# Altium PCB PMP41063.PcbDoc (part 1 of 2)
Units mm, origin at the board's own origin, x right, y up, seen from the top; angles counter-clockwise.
Board outline 173.28 x 60.81 mm, 2 copper layers (Top Layer, Bottom Layer), stack 1.575 mm thick; 103 components, 53 nets, 215 pads, 774 vias.
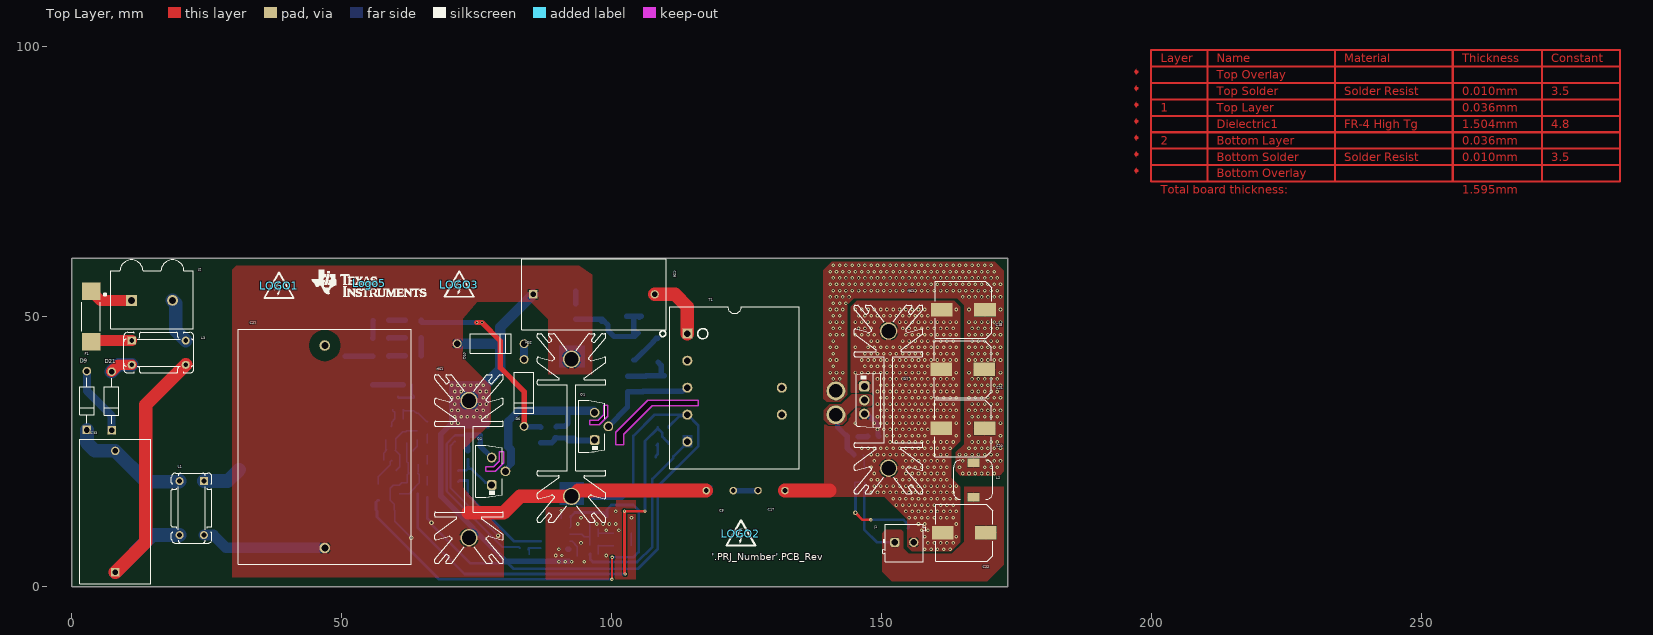
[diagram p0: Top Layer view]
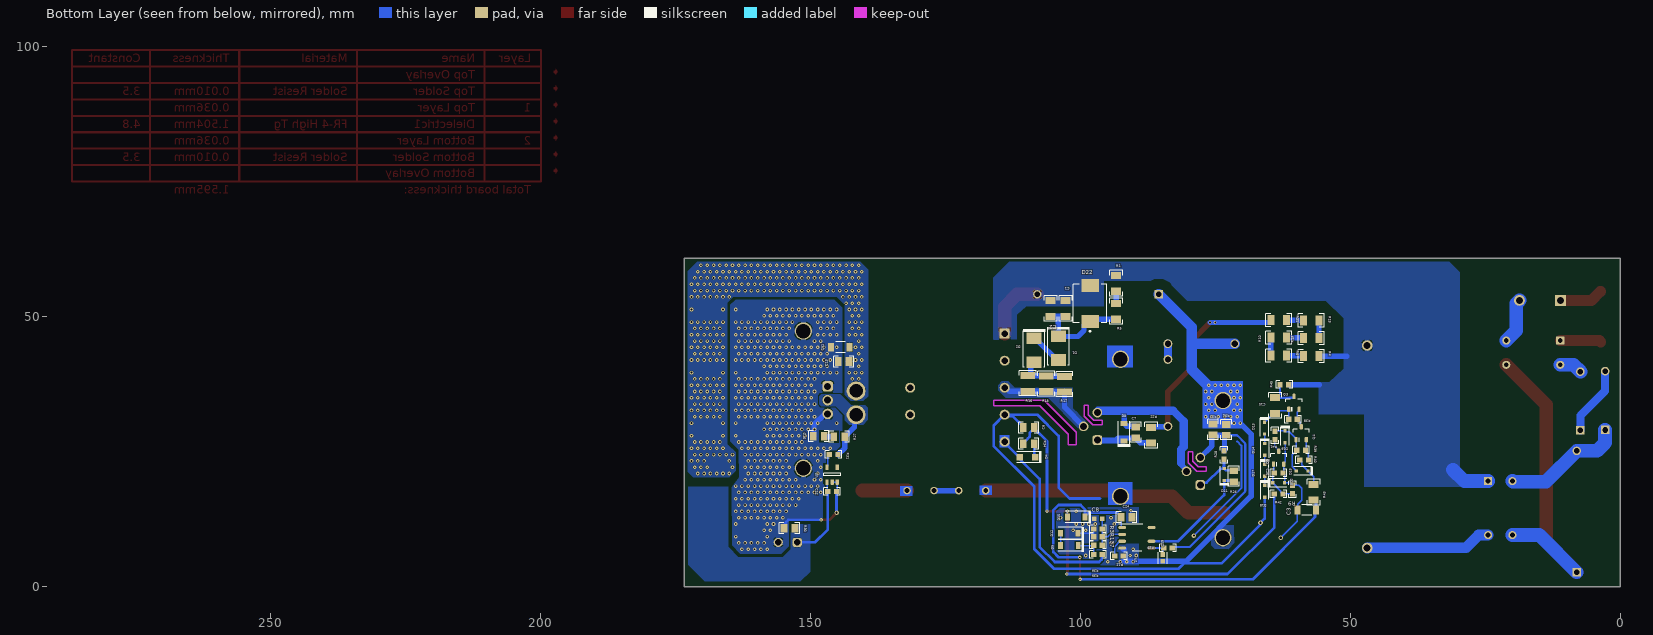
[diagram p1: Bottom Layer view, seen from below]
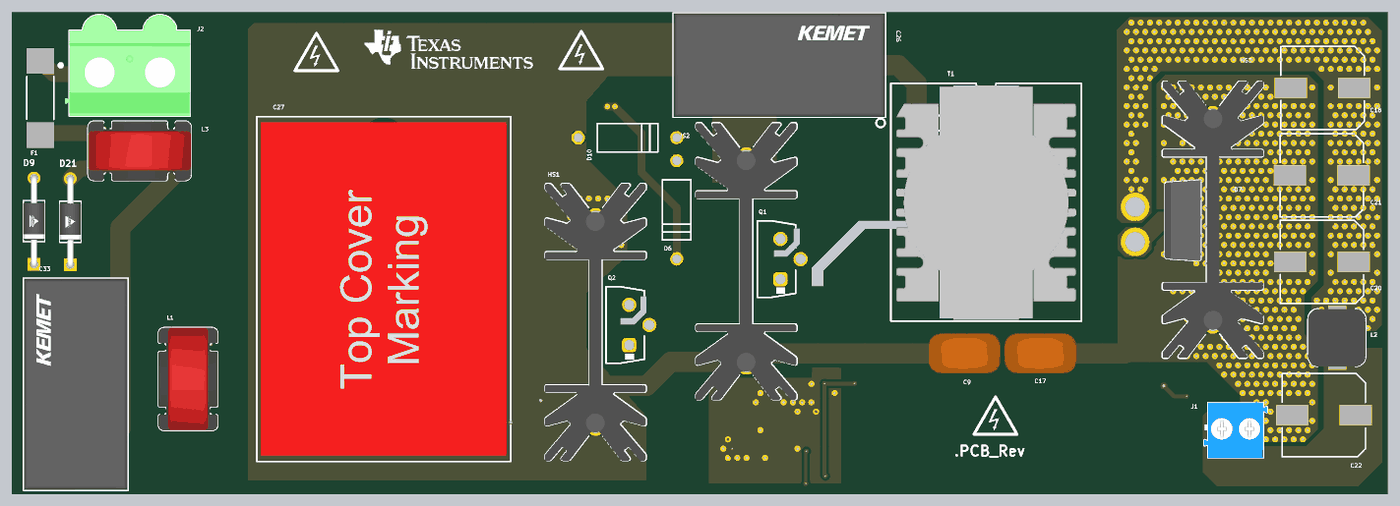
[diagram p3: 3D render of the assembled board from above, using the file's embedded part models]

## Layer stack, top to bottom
Top Solder: solder mask 0.0102, Solder Resist, Dk 3.5
Top Layer: signal copper 0.0356
Dielectric1: core 1.5037, FR-4 High Tg, Dk 4.8
Bottom Layer: signal copper 0.0356
Bottom Solder: solder mask 0.0102, Solder Resist, Dk 3.5

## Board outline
0,0 0,60.808 173.284,60.808 173.284,0
cut-out: 100.762,26.238 100.762,28.607 105.618,33.464 106.673,34.519 116.018,34.519 116.018,33.464 107.497,33.464 102.21,28.177 102.21,26.238
cut-out: 95.944,29.957 95.944,30.795 97.442,30.795 98.458,31.811 98.458,33.564 99.246,33.564 99.246,31.55 97.653,29.957
cut-out: 76.632,21.387 76.632,22.225 78.13,22.225 79.146,23.241 79.146,24.994 79.934,24.994 79.934,22.911 78.41,21.387

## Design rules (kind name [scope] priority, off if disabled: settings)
AcuteAngle [All] p1: minimum=4.50000000000000E+0001 checktracksonly=FALSE
AssemblyTestPointUsage [All] p1: valid=2
BoardOutlineClearance BoardOutlineClearance_MountingHoles [OnCopper and InComponentClass('Mounting Holes')] p1: gap=1 ignorepadtopadclearanceinfootprint=FALSE
BoardOutlineClearance BoardOutlineClearance_Poly [OnCopper and IsPoly] p2: gap=0.635 ignorepadtopadclearanceinfootprint=FALSE
BoardOutlineClearance [OnCopper and Not InComponentClass('Logo') and not InComponentClass('FiducialMark') and not InRegion(1000,500,4000,800) and not InPoly] p3: gap=1.016 ignorepadtopadclearanceinfootprint=FALSE
Clearance "HV LV" [InNetClass('HV') vs InNetClass('LV')] p1: gap=1.9 ignorepadtopadclearanceinfootprint=TRUE
Clearance [All] p2: gap=0.3 ignorepadtopadclearanceinfootprint=FALSE
Clearance Clearance_Poly [InPolygon] p3: gap=0.3 ignorepadtopadclearanceinfootprint=TRUE
Clearance Clearance_FiducialMark [IsKeepOut and InComponentClass('FiducialMark') vs IsPad and InComponentClass('FiducialMark')] p4: gap=0.3 ignorepadtopadclearanceinfootprint=FALSE
ComponentClearance ComponentClearance_MountingHoles_FiducialMarks [InComponentClass('Mounting Holes') vs InComponentClass('FiducialMark')] p1: gap=1.27 collisioncheckmode=3 verticalgap=0.254 showdistances=FALSE
ComponentClearance ComponentClearance_Shunt [InComponentClass('Header') vs InComponentClass('Shunt')] p2: gap=0 collisioncheckmode=3 verticalgap=0 showdistances=FALSE
ComponentClearance ComponentClearance_Logo [InComponentClass('Logo')] p3: gap=0.762 collisioncheckmode=3 verticalgap=0.254 showdistances=FALSE
ComponentClearance ComponentClearance_ScrewToNut [(HasFootprint('NY PMS 440 0025 PH')) vs (HasFootprint('Keystone_1902C'))] p4: gap=0.127 collisioncheckmode=3 verticalgap=0.254 showdistances=FALSE
ComponentClearance ComponentClearance_MountingHoles [InComponentClass('Mounting Holes')] p5: gap=2.54 collisioncheckmode=3 verticalgap=2540 showdistances=FALSE
ComponentClearance ComponentClearance_SmallPassives [HasFootprint('0201*') or HasFootprint('0402*') or HasFootprint('0508') or HasFootprint('0603*') or HasFootprint('0612') or HasFootprint('0805*') or HasFootprint('0815*') or HasFootprint('0830*') or HasFootprint('1206*') or HasFootprint('1210*') or HasFootprint('1808*') or HasFootprint('1812*') or HasFootprint('1825*') or HasFootprint('2010*') or HasFootprint('2220*') or HasFootprint('2225*') or HasFootprint('2512*') or HasFootprint('2728*') or HasFootprint('3518*') vs HasFootprint('0201*') or HasFootprint('0402*') or HasFootprint('0508') or HasFootprint('0603*') or HasFootprint('0612') or HasFootprint('0805*') or HasFootprint('0815*') or HasFootprint('0830*') or HasFootprint('1206*') or HasFootprint('1210*') or HasFootprint('1808*') or HasFootprint('1812*') or HasFootprint('1825*') or HasFootprint('2010*') or HasFootprint('2220*') or HasFootprint('2225*') or HasFootprint('2512*') or HasFootprint('2728*') or HasFootprint('3518*')] p6: gap=0.38 collisioncheckmode=3 verticalgap=0.254 showdistances=FALSE
ComponentClearance ComponentClearance_THtoSMT [IsThruComponent vs IsSMTComponent] p7: gap=0.762 collisioncheckmode=3 verticalgap=0.762 showdistances=FALSE
ComponentClearance ComponentClearance_THtoTH [IsThruComponent vs IsThruComponent] p8: gap=0.508 collisioncheckmode=3 verticalgap=0.762 showdistances=FALSE
ComponentClearance [All] p9: gap=0.3 collisioncheckmode=3 verticalgap=0.254 showdistances=FALSE
DiffPairsRouting [All] p1: maxlimit=2.54 minlimit=0.254 mostfreqgap=0.254 toplayer_minwidth=0.381 toplayer_maxwidth=0.381 toplayer_prefwidth=0.381 bottomlayer_minwidth=0.381 bottomlayer_maxwidth=0.381 bottomlayer_prefwidth=0.381 maxuncoupledlength=25.4
FabricationTestPointUsage TestPointUsage [All] p1: valid=2 allowmultiple=FALSE
FabricationTestpoint Testpoint [All] p1: side=3 testpointundercomponent=TRUE minsize=1.016 maxsize=2.54 preferedsize=1.524 minholesize=0 maxholesize=1.016 preferedholesize=0.813 testpointgrid=0.025 allowsidetop=TRUE allowsidebottom=TRUE usegrid=TRUE gridtolerance=0
FanoutControl Fanout_LCC [IsLCC] p1: bgadir=Out bgaviamode=Centered fanoutstyle=Auto fanoutdirection=Alternating viagrid=0.025 // Fanout_LCC (Default Rule)
FanoutControl Fanout_BGA [IsBGA] p2: bgadir=Out bgaviamode=Centered fanoutstyle=Auto fanoutdirection=Alternating viagrid=0.025 // Fanout_BGA (Default Rule)
FanoutControl Fanout_Default [All] p4: bgadir=Out bgaviamode=Centered fanoutstyle=Auto fanoutdirection=Alternating viagrid=0.025 // Fanout_Default (Default Rule)
FanoutControl Fanout_Small [(CompPinCount < 5)] p5: bgadir=Out bgaviamode=Centered fanoutstyle=Auto fanoutdirection=OutThenIn viagrid=0.025 // Fanout_Small (Default Rule)
HoleSize [All] p1: absolutevalues=TRUE maxlimit=6.375 minlimit=0.2 maxpercent=80.000 minpercent=20.000
MinimumAnnularRing MinimumAnnularRing_ThermalPadVias [IsVia and InAnyComponent] p1: minimumring=0.15
MinimumAnnularRing [All] p2: minimumring=0.2
MinimumSolderMaskSliver MinimumSolderMaskSliver_Logo [InComponentClass('Logo') vs InComponentClass('Logo')] p1: minsoldermaskwidth=0.018
MinimumSolderMaskSliver [All] p2: minsoldermaskwidth=0.1
PlaneConnect [All] p1: planeconnectstyle=Direct reliefexpansion=0.254 reliefentries=4 reliefconductorwidth=0.254 reliefairgap=0.254
PolygonConnect "PGND HV" [All vs IsNamedPolygon('TOP_LAYER_PGND_P010')] p1: thpad.connectstyle=Relief thpad.reliefconductorwidth=1 thpad.reliefentries=4 thpad.polygonreliefangle="90 Angle" thpad.airgapwidth=0.2 smdpad.connectstyle=Direct smdpad.reliefconductorwidth=0.254 smdpad.reliefentries=4 smdpad.polygonreliefangle="90 Angle" smdpad.airgapwidth=0.254 via.connectstyle=Direct via.reliefconductorwidth=0.254 via.reliefentries=4 via.polygonreliefangle="90 Angle" via.airgapwidth=0.254
PolygonConnect PolygonConnect_2 [All vs IsNamedPolygon('TOP_LAYER_SGND_P002')] p2: thpad.connectstyle=Relief thpad.reliefconductorwidth=1 thpad.reliefentries=4 thpad.polygonreliefangle="90 Angle" thpad.airgapwidth=0.2 smdpad.connectstyle=Direct smdpad.reliefconductorwidth=0.254 smdpad.reliefentries=4 smdpad.polygonreliefangle="90 Angle" smdpad.airgapwidth=0.254 via.connectstyle=Direct via.reliefconductorwidth=0.254 via.reliefentries=4 via.polygonreliefangle="90 Angle" via.airgapwidth=0.254
PolygonConnect PolygonConnect_1 [All vs IsNamedPolygon('BOTTOM_LAYER_SGND_P005')] p3: thpad.connectstyle=Relief thpad.reliefconductorwidth=1 thpad.reliefentries=4 thpad.polygonreliefangle="90 Angle" thpad.airgapwidth=0.2 smdpad.connectstyle=Direct smdpad.reliefconductorwidth=0.254 smdpad.reliefentries=4 smdpad.polygonreliefangle="90 Angle" smdpad.airgapwidth=0.254 via.connectstyle=Direct via.reliefconductorwidth=0.254 via.reliefentries=4 via.polygonreliefangle="90 Angle" via.airgapwidth=0.254
PolygonConnect [All vs IsNamedPolygon('BOTTOM_LAYER_VIN_P012')] p4: thpad.connectstyle=Relief thpad.reliefconductorwidth=1 thpad.reliefentries=4 thpad.polygonreliefangle="90 Angle" thpad.airgapwidth=0.2 smdpad.connectstyle=Direct smdpad.reliefconductorwidth=0.254 smdpad.reliefentries=4 smdpad.polygonreliefangle="90 Angle" smdpad.airgapwidth=0.254 via.connectstyle=Direct via.reliefconductorwidth=0.254 via.reliefentries=4 via.polygonreliefangle="90 Angle" via.airgapwidth=0.254
PolygonConnect PGND009 [All vs IsNamedPolygon('TOP_LAYER_PGND_P009')] p5: thpad.connectstyle=Relief thpad.reliefconductorwidth=1 thpad.reliefentries=4 thpad.polygonreliefangle="90 Angle" thpad.airgapwidth=0.5 smdpad.connectstyle=Direct smdpad.reliefconductorwidth=0.254 smdpad.reliefentries=4 smdpad.polygonreliefangle="90 Angle" smdpad.airgapwidth=0.254 via.connectstyle=Direct via.reliefconductorwidth=0.254 via.reliefentries=4 via.polygonreliefangle="90 Angle" via.airgapwidth=0.254
PolygonConnect SGND [All vs IsNamedPolygon('BOTTOM_LAYER_SGND_P004')] p6: thpad.connectstyle=Relief thpad.reliefconductorwidth=1 thpad.reliefentries=4 thpad.polygonreliefangle="90 Angle" thpad.airgapwidth=0.2 smdpad.connectstyle=Direct smdpad.reliefconductorwidth=0.254 smdpad.reliefentries=4 smdpad.polygonreliefangle="90 Angle" smdpad.airgapwidth=0.254 via.connectstyle=Direct via.reliefconductorwidth=0.254 via.reliefentries=4 via.polygonreliefangle="90 Angle" via.airgapwidth=0.254
RoutingVias ThermalPadVias [IsVia and InAnyComponent] p1: holewidth=0.2 width=0.5 viastyle="Through Hole" minholewidth=0.2 minwidth=0.5 maxholewidth=0.33 maxwidth=0.6
RoutingVias [All] p2: holewidth=0.406 width=0.864 viastyle="Through Hole" minholewidth=0.2 minwidth=0.61 maxholewidth=1.016 maxwidth=1.651
SilkToBoardRegionClearance [Not ((IsComment or IsDesignator) And (Hide <> 'False')) and not InRegion(1000,500,4000,800)] p1:
SilkToSilkClearance SilkToSilkClearance_Pb-FreeLogo [(HasFootprint('Pb-Free_Overlay_Medium') OR HasFootprint('Pb-Free_Overlay_Small')) vs (HasFootprint('Pb-Free_Overlay_Medium') OR HasFootprint('Pb-Free_Overlay_Small'))] p1: silktosilkclearance=0
SilkToSilkClearance [All] p2: silktosilkclearance=0.1
SilkToSolderMaskClearance SilkToComponentPadClearance [(IsPad or IsFill or IsRegion) and InAnycomponent] p1: minsilkscreentomaskgap=0.127 clearancetoexposedcopper=TRUE
SilkToSolderMaskClearance "Silk to Solder Mask Opening" [All] p2: minsilkscreentomaskgap=0.1 clearancetoexposedcopper=FALSE
SolderMaskExpansion [All] p1: expansion=0.05 istentingtop=FALSE
UnRoutedNet [All] p1: checkbadconnections=TRUE
Width [All] p1: maxlimit=2.54 minlimit=0.254 preferedwidth=1
14 further rules are at their usual default settings.

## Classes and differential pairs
component class Logo: Logo5
net class LV: AUX CS DRV NetC8_2 NetD4_1 NetD5_1 NetD5_2 NetD11_2 NetQ2_3 NetR12_2 PGND Vaux_rec VDD
net class HV: NetC1_2 NetC7_1 NetC7_2 NetD1_2 NetD2_2 NetD6_1 NetR1_1 NetR4_1 NetR6_1 NetR10_1 NetR13_1 NetR19_1 SW VIN
component class PMP41063_2_Hardware: LOGO1 LOGO2 LOGO3 Logo5 ZZ1 ZZ2 ZZ3 ZZ4
component class PMP41063_1000VDC: C1 C2 C3 C6 C7 C8 C9 C10 C11 C12 C13 C16 C17 C18 C19 C20 C21 C22 C24 C25 C26 C27 C33 D1 D2 D4 D5 D6 D7 D8 D9 D10 D11 D12 D13 D14 D15 D16 D17 D18 D19 D20 D21 D22 F1 HS1 HS2 HS3 J1 J2 L1 L2 L3 Q1 Q2 Q3 Q4 Q5 R1 R3 R4 R5 R6 R9 R10 R12 R13 R16 R17 R18 R19 R21 R22 R26 R27 R28 R29 R30 R31 R32 R33 R34 R35 R36 R38 R39 R40 R41 R42 R43 R45 R137 T1 U1 U2
component class AssemblyNote: ZZ1 ZZ2 ZZ3 ZZ4

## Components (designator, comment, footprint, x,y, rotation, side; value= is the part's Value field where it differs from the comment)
C1 "GRM31A7U3A331JW31D" 1206 102.702,51.505 r270 bottom value=330pF
C2 "VJ1206A471JXGAT5Z" 1206 105.469,51.499 r270 bottom value=470pF
C3 "C3216X5R1V226M160AC" 1206_180 58.01,14.174 r0 bottom value=22uF
C6 "GRM21BR6YA106KE43L" 0805_HV 109.516,29.457 r0 bottom value=10uF
C7 "CMP-0007711-2" 0805_HV 89.668,28.573 r90 bottom value=1000pF
C8 "885012006030" WCAP-CSGP_0603_L1.6W0.8H0.8_Reflow 96.625,12.551 r180 bottom
C9 "VY2222M35Y5UG6TV5" VY2_900x500_5 119.985,17.776 r0 top value=2200pF
C10 "1206Y1K01P50DAR" 1206 63.874,33.538 r270 bottom value=1.5pF
C11 "GRM31CR71E475KA88L" 1206_180 144.404,44.337 r0 bottom value=4.7uF
C12 "CMP-0007040-4" 0603 145.926,17.631 r180 bottom value=1uF
C13 "GRM21BR71E104KA01L" 0805_HV 143.794,41.685 r0 bottom value=0.1uF
C16 "C0805C222K2RAC" 0805_HV 148.41,27.838 r180 bottom value=2200pF
C17 "VY2222M35Y5UG6TV5" VY2_900x500_5 129.561,17.782 r0 top value=2200pF
C18 "EEHZC1E331P" SM_RADIAL_10BMM 165.105,51.261 r180 top value=330uF
C19 "GCG1885G1H220JA01D" FP-GCG1885G1H220JA01D_0603-IPC_C 84.689,5.311 r90 bottom value=22pF
C20 "EEHZC1E331P" SM_RADIAL_10BMM 165.029,29.315 r180 top value=330uF
C21 "EEHZC1E331P" SM_RADIAL_10BMM 165.003,40.237 r180 top value=330uF
C22 "EEHZC1E331P" SM_RADIAL_10BMM 165.278,9.982 r180 top value=330uF
C24 "GRM21BR6YA106KE43L" 0805_HV 91.394,12.831 r180 bottom value=10uF
C25 "GCJ188R71H224KA01D" 0603 63.226,21.034 r180 bottom value=0.22uF
C26 "R75TN312050H3J" FP-R75TN312050H3J_RADIAL-MFG 96.674,54.134 r0 top value=120nF
C27 "4.7µF/1KV Film cap" WCAP-FTBE_L42W31H43 46.837,25.9 r90 top
C33 "R75TN312050H3J" FP-R75TN312050H3J_RADIAL-MFG 8.02,13.883 r90 top value=120nF
D1 "RS1MB-13-F" SMB 104.018,44.174 r270 bottom value=1000V
D2 "RS1MB-13-F" SMB 108.539,43.768 r270 bottom value=1000V
D4 "RS1MWF-7" SOD-123F 109.751,23.98 r0 bottom value=1000V
D5 "1N4148W-7-F" SOD-123 101.989,7.607 r0 bottom value=100V
D6 "CMP-0006021-3" DO-15 83.746,35.876 r90 top value=300V
D7 "STPS20M100SFP" TO-220FP 146.758,34.527 r270 top value=100V
D8 "MMSZ4699-HE3-08" SOD-123 91.867,28.598 r90 bottom value=12V
D9 "1N4007-E3/53" FP-1N4007-E3/53_DO-41-MFG 2.769,34.452 r90 top
D10 "CMP-0006021-3" DO-15 77.551,44.985 r180 top value=300V
D11 "BAT54HT1G" SOD-323 73.312,20.756 r90 bottom value=30V
D12 "MMSZ4699T1G" SOD-123 102.015,9.876 r0 bottom value=12V
D13 "UDZLVFHTE-17130" SOD-323F 65.867,29.342 r270 bottom value=130V
D14 "UDZLVFHTE-17130" SOD-323F 65.791,25.405 r270 bottom value=130V
D15 "BAV21W-7-F" SOD-123 100.719,12.893 r0 bottom value=200V
D16 "MMSZ5254BS-7-F" SOD-323 62.032,27.744 r270 bottom value=27V
D17 "UDZLVFHTE-17130" SOD-323F 65.816,21.544 r270 bottom value=130V
D18 "UDZLVFHTE-17130" SOD-323F 65.816,17.658 r270 bottom value=130V
D19 "SZMM3Z18VST1G" SOD-323 58.889,21.413 r0 bottom value=18V
D20 "SZMM3Z18VST1G" SOD-323 63.226,19.21 r180 bottom value=18V
D21 "1N4007-E3/53" FP-1N4007-E3/53_DO-41-MFG 7.341,34.376 r90 top
D22 "SMCJ300A" FP-SMCJ300A_DO214AB-MFG 98.136,52.432 r90 bottom
F1 "0443001.DR" FUSE_0443 3.556,49.995 r90 top
HS1 "CMP-0004071-1" Aavid_513102B02500G 73.538,21.746 r90 top
HS2 "CMP-0004071-1" Aavid_513102B02500G 92.53,29.407 r90 top
HS3 "CMP-0004071-1" Aavid_513102B02500G 151.262,34.624 r270 top
J1 "1776275-2" TE_1776275-2 154.158,8.183 r0 top
J2 "1732720" Phoenix_1732720 14.825,54.109 r0 top
L1 "744821110" WE-CMB_XS 22.185,14.535 r270 top value=10mH
L2 "744777001" WE-PD_7345 166.959,19.74 r270 top value=1uH
L3 "744821201" WE-CMB_XS 16.072,43.325 r0 top value=1mH
LOGO1 "DANGER HIGH VOLTAGE" IEC_HighVoltage_Small 38.348,55.677 r0 top
LOGO2 "DANGER HIGH VOLTAGE" IEC_HighVoltage_Small 123.906,9.808 r0 top
LOGO3 "DANGER HIGH VOLTAGE" IEC_HighVoltage_Small 71.721,55.916 r0 top
Logo5 "Texas Instruments" TI_Stacked_Overlay_Small 55.021,56.165 r0 top
Q1 "STF2N95K5" TO-220_FullPAK_Offset 96.808,29.671 r90 top value=950V
Q2 "STF2N95K5" TO-220_FullPAK_Offset 77.749,21.356 r90 top value=800V
Q3 "BSS126H6906XTSA1" SOT-23 60.4,34.021 r90 bottom value=600V
Q4 "BSS126H6906XTSA1" SOT-23 59.06,28.43 r90 bottom value=600V
Q5 "NX7002AK,215" SOT-23 63.226,23.883 r90 bottom value=60V
R1 "CRCW12063M01FKEA" 1206 93.333,56.148 r90 bottom value=3.01Meg
R3 "RT0603BRD07142KL" 0603 96.686,10.666 r180 bottom value=142k
R4 "ERJ-8ENF2003V" 1206 57.206,42.672 r180 bottom value=200k
R5 "CRCW12063M01FKEA" 1206 93.331,50.962 r90 bottom value=3.01Meg
R6 "ERJ-8ENF2003V" 1206 63.211,42.782 r180 bottom value=200k
R9 "CRCW060356K0JNEA" 0603 60.66,17.986 r270 bottom value=56k
R10 "ERJ-8ENF2003V" 1206 63.211,46.106 r0 bottom value=200k
R12 "RC0603FR-0751K1L" 0603 92.82,5.634 r0 bottom value=51.1k
R13 "ERJ-8ENF2003V" 1206 57.176,46.023 r0 bottom value=200k
R16 "RC1210FR-07549RL" 1210 109.682,37.621 r90 bottom value=549
R17 "RC1210FR-07549RL" 1210 102.9,37.494 r90 bottom value=549
R18 "RC1210FR-07549RL" 1210 106.304,37.57 r90 bottom value=549
R19 "ERJ-8ENF2003V" 1206 57.222,49.278 r180 bottom value=200k
R21 "ERJ-8ENF2003V" 1206 63.227,49.336 r180 bottom value=200k
R22 "CRCW12060000Z0EA" 1206 86.862,28.057 r270 bottom value=0
R26 "CRCW080510R5FKEA" 0805_HV 71.558,20.439 r90 bottom value=10.5
R27 "RC0805FR-0710RL" 0805_HV 144.607,27.73 r0 bottom value=10.0
R28 "RC0603FR-07100KL" 0603 73.335,24.385 r90 bottom value=100k
R29 "CRCW0603309RFKEA" 0603 83.748,7.126 r180 bottom value=309
R30 "RT0805BRD0717K2L" 0805_HV 153.85,10.79 r180 bottom value=17.2k
R31 "CRCW06034R70JNEA" 0603 145.642,24.444 r180 bottom value=4.7
R32 "CRCW08051R54FKEA" 0805_HV 72.954,29.036 r270 bottom value=1.54
R33 "CRCW08051R54FKEA" 0805_HV 75.392,29.112 r270 bottom value=1.54
R34 "RC0805JR-075R6L" 0805_HV 109.519,26.435 r180 bottom value=5.6
R35 "RC0603JR-0720KL" 0603 96.687,5.964 r180 bottom value=20k
R36 "RT0603BRD0714K2L" 0603 96.687,7.659 r0 bottom value=14.2k
R38 "CRCW06031M00JNEA" 0603 60.553,30.982 r180 bottom value=1.0Meg
R39 "CRCW06031M00JNEA" 0603 59.06,25.261 r180 bottom value=1.0Meg
R40 "RC0603JR-075K1L" 0603 58.51,23.433 r180 bottom value=5.1k
R41 "CRCW060310K0FKEA" 0603 63.911,27.998 r270 bottom value=10.0k
R42 "RT0603BRD07130KL" 0603 63.226,17.163 r180 bottom value=130k
R43 "CRCW12060000Z0EA" 1206 56.759,17.458 r270 bottom value=0
R45 "CRCW06030000Z0EA" 0603 62.172,37.393 r0 bottom value=0
R137 "RC0603FR-0716KL" 0603 96.686,9.217 r180 bottom value=16.0k
T1 "ER28-14" ER28-14 113.993,46.84 r0 top locked
U1 "UCC28730DR" D0007A_N 89.491,9.032 r180 bottom
U2 "UCC24650DBVR" DBV0005A_N 145.926,20.734 r90 bottom
ZZ1 "This Assembly Note is for PCB labels only" AssemblyNoteLabel 217.399,-38.608 r0 top
ZZ2 "These assemblies are ESD sensitive, ESD precautions shall be observed." AssemblyNote 217.399,-41.374 r0 top
ZZ3 "These assemblies must be clean and free from flux and all contaminants. Use of no clean flux is not acceptable." AssemblyNote 217.399,-43.623 r0 top
ZZ4 "These assemblies must comply with workmanship standards IPC-A-610 Class 2, unless otherwise specified." AssemblyNote 217.399,-45.872 r0 top

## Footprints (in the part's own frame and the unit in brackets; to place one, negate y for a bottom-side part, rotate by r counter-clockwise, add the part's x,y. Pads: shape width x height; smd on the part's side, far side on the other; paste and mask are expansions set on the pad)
0603 [mm] "0603 from SM-752 data"
  rect 1x0.95 smd: 1(-0.8,0) 2(0.8,0)
  silkscreen extent -1.52,-0.69 1.52,0.69, body extent -0.87,-0.47 0.87,0.47, height 1
0805_HV [mil] "0805 with 30mil clearance between pads"
  rect 50x63 smd: 1(-40,0) 2(40,0)
  silkscreen extent -74,-40 74,40, body extent -43,-29 43,29, height 57
1206 [mm] "1206 from SM-752 data"
  rect 1.3x1.85 smd: 1(-1.45,0) 2(1.45,0)
  silkscreen extent -2.4,-1.21 2.4,1.21, body extent -1.7,-0.9 1.7,0.9, height 1.35
1206_180 [mm] "1206_180"
  rect 1.1x1.6 smd: 1(-1.7,0) 2(1.7,0)
  silkscreen extent -0.9,-1 0.9,1, body extent -1.75,-0.95 1.75,0.95, height 1.8
1210 [mm] "1210 from SM-752 data"
  rect 1.3x2.7 smd: 1(-1.45,0) 2(1.45,0)
  silkscreen extent -2.32,-1.57 2.32,1.57, body extent -1.7,-1.35 1.7,1.35, height 1.35
Aavid_513102B02500G [mm] "Heat Sink TO-220 Aluminum"
  round 3.2 hole 2.67: 1(-12.7,0) 2(12.7,0)
  silkscreen extent -17.46,-6.35 17.46,6.35, body extent -17.5,-6.3 17.42,6.4, height 38.1
AssemblyNote [mm] "Assembly Note"
AssemblyNoteLabel [mm] "Assembly Note for PCB Labels"
D0007A_N [mm] "SOIC, 7-Leads, Body 4.9x3.9mm, Pitch 1.27mm, IPC Medium Density"
  oval 1.45x0.6 smd: 1(-2.725,1.905) 2(-2.725,0.635) 3(-2.725,-0.635) 4(-2.725,-1.905) 5(2.725,-1.905) 6(2.725,-0.635) 8(2.725,1.905)
  silkscreen extent -3.32,-2.5 1.1,2.52, body extent -3.01,-2.45 3.01,2.45, height 1.75
DBV0005A_N [mm] "SOT23, 5-Leads, Body 2.9x1.6mm, Pitch 0.95mm, Lead Span 2.8mm, IPC Medium Density"
  rrect17% 1x0.6 smd: 1(-1.375,0.95) 2(-1.375,0) 3(-1.375,-0.95) 4(1.375,-0.95) 5(1.375,0.95)
  silkscreen extent -0.25,-1.55 0.25,1.55, body extent -1.42,-1.46 1.42,1.46, height 1.09
DO-15 [mm] "TH, 2-Leads, Dia 3.6mm, Pin Spacing 12.4mm"
  round 1.65 hole 1.15: 1(-6.2,0) 2(6.2,0)
  silkscreen extent -3.8,-1.8 3.8,1.8, body extent -6.65,-1.79 6.65,1.8, height 3.6
ER28-14 [mm]
  rect 1.85x1.85 hole 1.25: 1(-0.018,-0.006)
  round 1.85 hole 1.25: 2(-0.018,-5.006) 3(-0.018,-10.006) 4(-0.018,-15.006) 5(-0.018,-20.006) 7(17.482,-15.006) 8(17.482,-10.006)
  round 3.5 hole 2.5: A(27.5,-10.6) B(27.5,-15.006)
  silkscreen extent -5.12,-25.01 20.73,4.99, body extent -2.6,-24.81 20.06,4.71, height 36.2
FP-1N4007-E3/53_DO-41-MFG [mm]
  rrect6% 1.6x1.6 hole 1.05 paste-1000 mask+0: 1(-5.438,0)
  round 1.6 hole 1.05 paste-1000 mask+0: 2(5.438,0)
  silkscreen extent -4.24,-1.35 4.24,1.35, body extent -6.34,-1.45 6.34,1.45, height 0.25
FP-GCG1885G1H220JA01D_0603-IPC_C [mm]
  rrect12% 0.855x0.812 smd paste+0 mask+0: 1(-0.625,0) 2(0.625,0)
  silkscreen extent -1.05,-0.85 1.05,0.85, body extent -0.8,-0.4 0.8,0.4, height 0.9
FP-R75TN312050H3J_RADIAL-MFG [mm]
  rrect6% 1.55x1.55 hole 1 paste-1000 mask+0: 1(-11.25,0)
  round 1.55 hole 1 paste-1000 mask+0: 2(11.25,0)
  silkscreen extent -13.4,-6.6 13.4,6.6, body extent -13.5,-6.7 13.5,6.7, height 0.25
FP-SMCJ300A_DO214AB-MFG [mm]
  rrect4% 2.4x3.3 smd paste+0 mask+0: 1(-3.3,0) 2(3.3,0)
  silkscreen extent -5.27,-3.11 3.55,3.11, body extent -3.97,-2.95 3.97,2.95, height 2.62
FUSE_0443 [mm] "LITTELFUSE"
  rect 3.25x3.43 smd: 1(-4.675,0) 2(4.675,0)
  silkscreen extent -2.7,-1.7 2.7,1.7, body extent -5.05,-1.56 5.05,1.56, height 3.12
IEC_HighVoltage_Small [mm]
  silkscreen extent -2.72,-2.24 2.72,2.47
Phoenix_1732720 [mm] "Phoenix Contact"
  rect 2x2 hole 1.3 paste+0 mask+0.05: 1(-3.81,-1.1)
  round 2 hole 1.3 paste+0 mask+0.05: 2(3.81,-1.1)
  silkscreen extent -8.91,-6.4 7.62,6.4, body extent -8.19,-6.4 7.62,6.4, height 18.3
SM_RADIAL_10BMM [mm] "Nichicon 10x10"
  rect 4x2.5 smd: 1(-4,0) 2(4,0)
  silkscreen extent -5.25,-5.25 5.25,5.25, body extent -5.25,-5.25 5.25,5.25, height 10.5
SMB [mm] "Molded Diode, 2-Leads, Body 5.4x3.6mm, IPC Medium Density, based on OnSemi component dimensions"
  rect 2.159x2.743 smd: 1(-2.21,0) 2(2.21,0)
  silkscreen extent -3.94,-2.08 3.18,2.08, body extent -2.7,-1.8 2.7,1.8, height 2.32
SOD-123 [mm] "On Semi recommended land pattern"
  rect 0.915x1.22 smd: 1(-1.637,0) 2(1.637,0)
  silkscreen extent -2.74,-1.17 2.03,1.17, body extent -1.93,-0.9 1.93,0.9, height 1.35
SOD-123F [mm] "NXP recommended land pattern"
  rect 1.2x1.2 smd paste-0.05: 1(-1.4,0) 2(1.4,0)
  silkscreen extent -2.64,-1.12 2.01,1.12, body extent -1.8,-0.85 1.8,0.85, height 1.2
SOD-323 [mm] "NXP recommended land pattern"
  rect 0.6x0.6 smd paste-0.05: 1(-1.1,0) 2(1.1,0)
  silkscreen extent -2.05,-0.86 1.53,0.86, body extent -1.3,-0.67 1.3,0.68, height 1.1
SOD-323F [mm] "NXP recommended land pattern"
  rect 0.6x0.6 smd paste-0.05: 1(-1.1,0) 2(1.1,0)
  silkscreen extent -2.06,-0.86 1.53,0.87, body extent -1.35,-0.67 1.35,0.67, height 0.79
SOT-23 [mm] "SOT23, 3-Leads, Body 2.9x1.3mm, Pitch 0.95mm, Lead Span 2.5mm, IPC Medium Density"
  rrect50% 1x0.6 smd: 1(-1.2,0.95) 2(-1.2,-0.95) 3(1.2,0)
  silkscreen extent -1.62,-1.5 0.7,1.5, body extent -1.16,-1.45 1.21,1.45, height 1
TE_1776275-2 [mm] "Terminal Block, 3.5mm, 2x1, TH"
  rrect50% 1.7x1.7 hole 1.2: 1(-1.75,0)
  round 1.7 hole 1.2: 2(1.75,0)
  silkscreen extent -3.99,-3.58 3.99,3.4, body extent -3.99,-3.58 3.99,3.4, height 8.28
TI_Stacked_Overlay_Small [mm]
  silkscreen extent -10.63,-2.49 10.63,2.49
TO-220_FullPAK_Offset [mm] "Infineon  PG-TO220-3-31"
  rrect50% 1.8x1.8 hole 1.3: 1(-2.54,0)
  round 1.8 hole 1.3: 2(0,-2.54) 3(2.54,0)
  silkscreen extent -4.82,-1.91 4.83,2.92, body extent -4.82,-2.84 4.83,2.92, height 22.91
TO-220FP [mm] "FM, Body 10.4x4.6mm, Pitch 2.55mm"
  rrect50% 1.95x1.95 hole 1.3: 1(-2.55,0)
  round 1.95 hole 1.3: 2(0,0) 3(2.55,0)
  silkscreen extent -5.1,-1.5 5.08,3, body extent -5.09,-1.5 5.09,3, height 19.41
VY2_900x500_5 [mm] "TH, 2-Leads, Body 9x5mm, Lead Spacing 5mm"
  round 1.4 hole 0.9: 1(-2.5,0) 2(2.5,0)
  body extent -4.5,-2.5 4.5,2.5, height 13
WCAP-CSGP_0603_L1.6W0.8H0.8_Reflow [mm] "Ceramic Capacitors, body 1.6x0.8mm"
  rect 0.8x0.8 smd: 1(-0.75,0) 2(0.75,0)
  body extent -0.8,-0.4 0.8,0.4, height 0.8
WCAP-FTBE_L42W31H43 [mm] "THT Film Capacitors, body 42x31mm"
  round 1.95 hole 1.3: 1(-18.75,0) 2(18.75,0)
  silkscreen extent -21.75,-16 21.75,16, body extent -21,-15.5 21,15.5, height 43.05
WE-CMB_XS [mm] "WE-CMB Series Size XS"
  rect 1.5x1.5 hole 0.9: 1(-5,2.25)
  round 1.5 hole 0.9: 2(-5,-2.25) 3(5,-2.25) 4(5,2.25)
  silkscreen extent -6.5,-3.75 6.5,3.75, body extent -6.5,-3.75 6.5,3.75, height 16.24
WE-PD_7345 [mm] "SMD Inductor, 2-Leads, Body 7,3x7,3mm"
  rect 1.6x2.2 smd: 1(-3.2,0) 2(3.2,0)
  silkscreen extent -3.65,-3.68 3.61,3.6, body extent -3.65,-3.68 3.65,3.6, height 4.49

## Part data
C1: library part CMP-0008900-1, "CAP, CERM, 330 pF, 1000 V, +/- 5%, U2J, 1206", Cap_Case=1206, Manufacturer=MuRata, Supplier Part Number 1=490-4304-1-ND, TempCo=U2J, Tolerance_%=5%, Value1=Unknown, Value2=1000V, ValueDisplayed=330pF
C2: library part CMP-0009035-1, "CAP, CERM, 470 pF, 1000 V, +/- 5%, C0G/NP0, 1206", Cap_Case=1206, Manufacturer=Vishay-Vitramon, Supplier Part Number 1=720-1016-1-ND, TempCo=C0G/NP0, Tolerance_%=5%, Value1=Unknown, Value2=1000V, ValueDisplayed=470pF
C3: library part CMP-0008667-2, "CAP, CERM, 22 uF, 35 V, +/- 20%, X5R, 1206", Cap_Case=1206_180, Manufacturer=TDK, Supplier Part Number 1=445-8045-1-ND, TempCo=X5R, Tolerance_%=20%, Value1="0.002398 ohm", Value2=35V, ValueDisplayed=22uF
C6 C24: library part CMP-0008310-2, "CAP, CERM, 10 uF, 35 V, +/- 10%, X5R, 0805", Cap_Case=0805, Manufacturer=MuRata, Supplier Part Number 1=490-10514-1-ND, TempCo=X5R, Tolerance_%=10%, Value1=Unknown, Value2=35V, ValueDisplayed=10uF
C7: "CAP, CERM, 1000 pF, 50 V, +/- 5%, X7R, 0805", Cap_Case=0805, Manufacturer=Kemet, PartNumber=C0805C102J5RACTU, Supplier Part Number 1=399-1149-1-ND, TempCo=X7R, Tolerance_%=5%, Value1="0.384 ohm", Value2=50V, ValueDisplayed=1000pF
C8: library part CMP-0107774-1, "WCAP-CSGP Multilayer Ceramic Chip Capacitor, General Purpose, size 0603, NP0, 4.7pF, 25VDC", Capacitance Tolerance=+/-0.5pF, Case/Size Code=0603, Insulation Resistance=10GOhm, Manufacturer="Wurth Elektronik", Operating Temperature Max=125°C, Operating Temperature Min=-55°C, Rated Voltage (DC)=25V
C9 C17: library part CMP-0080613-1, "CAP, CERM, 2200 pF, X1 440 VAC/Y2 300 VAC, +/- 20%, Y5U, Body9x5mm", Cap_Case=9x5mm, Manufacturer=Vishay-Bccomponents, TempCo=Y5U, Tolerance_%=20%, ValueDisplayed=2200pF
C10: library part CMP-0008597-2, "CAP, CERM, 1.5 pF, 1000 V, COG/NPO, 1206", Cap_Case=1206, Manufacturer="Knowles Syfer", Supplier Part Number 1=1206Y1K01P50DAR-ND, TempCo=C0G/NP0, Tolerance_%=0.5pF, Value1="0.665 ohm", Value2=1000V, ValueDisplayed=1.5pF
C11: library part CMP-0008967-2, "CAP, CERM, 4.7 uF, 25 V, +/- 10%, X7R, 1206", Cap_Case=1206, Manufacturer=MuRata, Supplier Part Number 1=490-1809-1-ND, TempCo=X7R, Tolerance_%=10%, Value1=Unknown, Value2=25V, ValueDisplayed=4.7uF
C12: "CAP, CERM, 1 uF, 25 V, +/- 10%, X7R, 0603", Cap_Case=0603, Manufacturer=TDK, PartNumber=C1608X7R1E105K080AB, Supplier Part Number 1=445-5956-1-ND, TempCo=X7R, Tolerance_%=10%, Value1=Unknown, Value2=25V, ValueDisplayed=1uF
C13: library part CMP-0008335-2, "CAP, CERM, 0.1 uF, 25 V, +/- 10%, X7R, 0805", Cap_Case=0805, Manufacturer=MuRata, Supplier Part Number 1=490-1673-1-ND, TempCo=X7R, Tolerance_%=10%, Value1=Unknown, Value2=25V, ValueDisplayed=0.1uF
C16: library part CMP-0007765-2, "CAP, CERM, 2200 pF, 200 V, +/- 10%, X7R, 0805", Cap_Case=0805, Manufacturer=Kemet, Supplier Part Number 1=399-8045-1-ND, TempCo=X7R, Tolerance_%=10%, Value1=Unknown, Value2=200V, ValueDisplayed=2200pF
C18 C20 C21 C22: library part CMP-0012593-3, "CAP, Polymer Hybrid, 330 uF, 25 V, +/- 20%, 20 ohm, 10x10 SMD", Manufacturer=Panasonic, Supplier Part Number 1=P15459CT-ND, Tolerance_%=20%, Value1="20 ohm", Value2=25V, ValueDisplayed=330uF
C19: library part CMP-0095693-1, "AgPd Termination Conductive Glue Mounting Chip Multilayer Ceramic Capacitors for Automotive 22pF with 5% as tolerance, 50V X8G 30ppm/°C, 0603 Package", Manufacturer=Murata, Operating Temperature Range="-55°C to +150°C", TempCo=30ppm/°C, Temperature Characteristic=X8G, Tolerance_%=0.05%, ValueDisplayed=22pF
C25: library part CMP-0079579-1, "CAP, CERM, 0.22 µF, 50 V,+/- 10%, X7R, AEC-Q200 Grade 1, 0603", Cap_Case=0603, Manufacturer=MuRata, Supplier Part Number 1=490-14410-1-ND, TempCo=X7R, Tolerance_%=10%, Value2=50V, ValueDisplayed=0.22µF
C26 C33: library part CMP-0095721-1, "0.12 µF Film Capacitor 650V 1600V (1.6kV) Polypropylene (PP), Metallized Radial", Digikey Part Number=399-R75TN312050H3J-ND, Manufacturer=KEMET, Mouser Part Number=80-R75TN312050H3J, Operating Temperature Range="-55°C to +125°C", Tolerance_%=5%, ValueDisplayed=0.12uF
C27: library part 890493428013CS, "WCAP-FTBE Film Capacitor, THT, L42 x W31 x H43mm, 4.7µF, 1000V", Capacitance=4.7µF, Capacitance Tolerance=+/-10%, Insulation Resistance="3000Ω x F", Manufacturer="Wurth Elektronik", Operating Temperature Max=85°C, Operating Temperature Min=-40°C, Rate of Voltage Rise=16V/µs, Rated Voltage (DC)=1000V
D1 D2: library part CMP-0076889-1, "Diode, P-N, 1000 V, 1 A, SMB", Manufacturer="Diodes Inc.", Supplier Part Number 1=RS1MB-FDICT-ND, Value1=1A, Value2=1.3V
D4: library part CMP-0082234-2, "Diode, Fast Rectifier, 1000 V, 1 A, SOD-123F", Manufacturer="Diodes Inc.", Value1=1A, Value2=1.3V
D5: library part CMP-0029001-1, "Diode, Ultrafast, 100 V, 0.15 A, SOD-123", Manufacturer="Diodes Inc.", Supplier Part Number 1=1N4148W-FDICT-ND, Value1=0.15A, Value2=1.25V
D6 D10: "Diode, TVS, Uni, 300 V, 482 Vc, DO-15", Manufacturer="Fairchild Semiconductor", PartNumber=P6KE350A, Value1=600W
D7: library part CMP-0028887-2, "Diode, Schottky, 100 V, 20 A, TH", Manufacturer=STMicroelectronics, Supplier Part Number 1=497-12637-5-ND, Value1=20A, Value2=0.85V
D8: library part CMP-0077572-3, "Diode, Zener, 12 V, 500 mW, AEC-Q101, SOD-123", Manufacturer=Vishay-Semiconductor, Power_W=500mW, Value1=0.5W
D9 D21: library part CMP-0096268-1, "Diode Standard 1000 V 1A Through Hole DO-204AL (DO-41)", Digikey Part Number=1N4007-E3/53GICT-ND, Forward Current=1A, Manufacturer=Vishay, Max Surge Forward Current=30A, Mouser Part Number=625-1N4007-E3/53, Operating Temperature Range="-50°C to +150°C", Peak Reverse Current=5uA, ValueDisplayed=15pF
D11: library part CMP-0028455-2, "Diode, Schottky, 30 V, 0.2 A, SOD-323", Manufacturer="ON Semiconductor", Value1=0.2A, Value2=0.35V
D12: library part CMP-0005742-3, "Diode, Zener, 12 V, 500 mW, SOD-123", Manufacturer="ON Semiconductor", Power_W=500mW, Value1=0.5W
D13 D14 D17 D18: library part CMP-0082118-3, "Diode, Zener, 130 V, 200 mW, SOD-323F, AEC-Q101", Manufacturer=Rohm, Power_W=200mW, Value1=0.2W
D15: library part CMP-0029031-2, "Diode, Switching, 200 V, 0.2 A, SOD-123", Manufacturer="Diodes Inc.", Value1=0.2A, Value2=1.25V
D16: library part CMP-0005839-3, "Diode, Zener, 27 V, 200 mW, SOD-323", Manufacturer="Diodes Inc.", Power_W=200mW, Value1=0.2W
D19 D20: library part CMP-0085765-1, "Diode, Zener, 18 V, 300 mW, AEC-Q101, SOD-323", Manufacturer="ON Semiconductor", Power_W=300mW, Value1=0.3W
D22: library part CMP-0088475-2, "486V Clamp 3.1A Ipp Tvs Diode Surface Mount DO-214AB (SMCJ)", Breakdown Voltage=335V, Clamping Voltage=486V, Digikey Part Number=SMCJ300ALFCT-ND, Manufacturer="Littelfuse Inc", Mouser Part Number=576-SMCJ300A, Operating Temperature Range="-65°C to +150°C"
F1: library part CMP-0003467-2, "Fuse, 1 A, 250VAC/VDC, SMD", Irating_A=1A, Manufacturer=Littelfuse, Supplier Part Number 1=F2906CT-ND
HS1 HS2 HS3: "Extruded heat sink with radial fins", Manufacturer=Aavid, PartNumber=513102B02500G, Supplier Part Number 1=HS346-ND
J1: library part CMP-0054987-1, "Terminal Block, 3.5mm, 2x1, Tin, TH", Color=Blue, Current_A=7A, Manufacturer="TE Connectivity", Supplier Part Number 1=A98036-ND, Voltage_V=250V
J2: library part CMP-0055482-1, "Terminal Block, 2x1, 7.62mm, TH", Manufacturer="Phoenix Contact", Supplier Part Number 1=277-6734-ND
L1: library part CMP-0076840-1, "Coupled inductor, 10 mH, 0.7 A, 0.35 ohm, TH", Manufacturer="Wurth Elektronik", Supplier Part Number 1=732-1437-ND, ValueDisplayed=10mH
L2: library part CMP-0064262-1, "Inductor, Shielded Drum Core, Metal Composite, 1 uH, 8 A, 0.0084 ohm, SMD", Manufacturer="Wurth Elektronik", Supplier Part Number 1=732-1924-ND, Value1="0.0084 ohm", Value2=8A, ValueDisplayed=1uH
L3: library part CMP-0013113-2, "Coupled inductor, 1 mH, 2 A, 0.045 ohm, TH", Manufacturer="Wurth Elektronik", Supplier Part Number 1=732-1435-ND, ValueDisplayed=1mH
LOGO1 LOGO2 LOGO3: library part CMP-0074835-1, "IEC 61010-1 High Voltage Warning"
Logo5: library part CMP-0074838-1, "Texas Instrument Corporate Signature"
Q1: library part CMP-0001279-3, "MOSFET N-CH 950V 2A TO220FP", Alternate Manufacturer=None, Manufacturer=STMicroelectronics, PartNumber=STF10N80K5, Value2="22 nC"
Q2: library part CMP-0001279-3, "MOSFET, N-CH, 800 V, 9 A, TO-220FP", Alternate Manufacturer=None, Manufacturer=STMicroelectronics, PartNumber=STF10N80K5, Supplier Part Number 1=497-15113-5-ND, Value2="22 nC"
Q3 Q4: library part CMP-0001147-4, "MOSFET, N-CH, Depletion Mode, 600 V, 0.021 A, SOT-23, AEC-Q101", Manufacturer="Infineon Technologies", Supplier Part Number 1=BSS126H6906XTSA1CT-ND, Value2="1.4 nC"
Q5: library part CMP-0000769-1, "MOSFET, N-CH, 60 V, 0.19 A, SOT-23", Manufacturer="Nexperia USA Inc", Supplier Part Number 1=1727-1289-1-ND
R1 R5: library part CMP-0016956-3, "RES, 3.01 M, 1%, 0.25 W, AEC-Q200 Grade 0, 1206", Manufacturer=Vishay-Dale, Power_W=250mW, Supplier Part Number 1=541-3.01MFCT-ND, TempCo="100 ppm/C", Tolerance_%=1%, Value2=0.25W, Value_Code=3M01, ValueDisplayed=3.01M
R3: library part CMP-0023744-1, "RES, 142 k, 0.1%, 0.1 W, 0603", Manufacturer="Yageo America", Power_W=100mW, TempCo="25 ppm/C", Tolerance_%=0.1%, Value2=0.1W, Value_Code=142k
R4 R6 R10 R13 R19 R21: library part CMP-0017437-3, "RES, 200 k, 1%, 0.25 W, AEC-Q200 Grade 0, 1206", Manufacturer=Panasonic, Power_W=250mW, Supplier Part Number 1=P200KFCT-ND, TempCo="100 ppm/C", Tolerance_%=1%, Value2=0.25W, Value_Code=200k
R9: library part CMP-0025828-4, "RES, 56 k, 5%, 0.1 W, AEC-Q200 Grade 0, 0603", Manufacturer=Vishay-Dale, Power_W=100mW, Supplier Part Number 1=541-56KGCT-ND, TempCo="200 ppm/C", Tolerance_%=5%, Value2=0.1W, Value_Code=56k0, ValueDisplayed=56k
R12: library part CMP-0023166-5, "RES, 51.1 k, 1%, 0.1 W, 0603", Manufacturer=Yageo, Power_W=100mW, Supplier Part Number 1=311-51.1KHRCT-ND, TempCo="100 ppm/C", Tolerance_%=1%, Value2=0.1W, Value_Code=51k1, ValueDisplayed=51.1k
R16 R17 R18: library part CMP-0083252-1, "RES, 549, 1%, 0.5 W, 1210", Manufacturer=Yageo, Power_W=500mW, TempCo="100 ppm/C", Tolerance_%=1%, Value2=0.5W, Value_Code=549R, ValueDisplayed=549
R22 R43: library part CMP-0018573-3, "RES, 0, 5%, 0.25 W, AEC-Q200 Grade 0, 1206", Manufacturer=Vishay-Dale, Power_W=250mW, Supplier Part Number 1=541-0.0ECT-ND, TempCo="200 ppm/C", Tolerance_%=5%, Value2=0.25W, Value_Code=0000, ValueDisplayed=0
R26: library part CMP-0020849-3, "RES, 10.5, 1%, 0.125 W, AEC-Q200 Grade 0, 0805", Manufacturer=Vishay-Dale, Power_W=125mW, Supplier Part Number 1=541-10.5CCT-ND, TempCo="100 ppm/C", Tolerance_%=1%, Value2=0.125W, Value_Code=10R5, ValueDisplayed=10.5
R27: library part CMP-0021863-2, "RES, 10.0, 1%, 0.125 W, 0805", Manufacturer="Yageo America", Power_W=125mW, Supplier Part Number 1=311-10.0CRCT-ND, TempCo="200 ppm/C", Tolerance_%=1%, Value2=0.125W, Value_Code=10R0, ValueDisplayed=10.0
R28: library part CMP-0022735-5, "RES, 100 k, 1%, 0.1 W, 0603", Manufacturer=Yageo, Power_W=100mW, Supplier Part Number 1=311-100KHRCT-ND, TempCo="100 ppm/C", Tolerance_%=1%, Value2=0.1W, Value_Code=100k
R29: library part CMP-0022323-5, "RES, 309, 1%, 0.1 W, AEC-Q200 Grade 0, 0603", Manufacturer=Vishay-Dale, Power_W=100mW, Supplier Part Number 1=541-309HCT-ND, TempCo="100 ppm/C", Tolerance_%=1%, Value2=0.1W, Value_Code=309R, ValueDisplayed=309
R30: library part CMP-0019626-1, "RES, 17.2 k, 0.1%, 0.125 W, 0805", Manufacturer="Yageo America", Power_W=125mW, TempCo="25 ppm/C", Tolerance_%=0.1%, Value2=0.125W, Value_Code=17k2, ValueDisplayed=17.2k
R31: library part CMP-0025821-1, "RES, 4.7, 5%, 0.1 W, 0603", Manufacturer=Vishay-Dale, Power_W=100mW, Supplier Part Number 1=541-4.7GCT-ND, TempCo="200 ppm/C", Tolerance_%=5%, Value2=0.1W, Value_Code=4R70, ValueDisplayed=4.7
R32 R33: library part CMP-0021027-1, "RES, 1.54, 1%, 0.125 W, 0805", Manufacturer=Vishay-Dale, Power_W=125mW, Supplier Part Number 1=541-1.54CCCT-ND, TempCo="100 ppm/C", Tolerance_%=1%, Value2=0.125W, Value_Code=1R54, ValueDisplayed=1.54
R34: library part CMP-0020824-1, "RES, 5.6, 5%, 0.125 W, 0805", Manufacturer="Yageo America", Power_W=125mW, Supplier Part Number 1=311-5.6ARCT-ND, TempCo="200 ppm/C", Tolerance_%=5%, Value2=0.125W, Value_Code=5R60, ValueDisplayed=5.6
R35: library part CMP-0025900-5, "RES, 20 k, 5%, 0.1 W, 0603", Manufacturer=Yageo, Power_W=100mW, Supplier Part Number 1=311-20KGRCT-ND, TempCo="100 ppm/C", Tolerance_%=5%, Value2=0.1W, Value_Code=20k0, ValueDisplayed=20k
R36: library part CMP-0023754-1, "RES, 14.2 k, 0.1%, 0.1 W, 0603", Manufacturer="Yageo America", Power_W=100mW, TempCo="25 ppm/C", Tolerance_%=0.1%, Value2=0.1W, Value_Code=14k2, ValueDisplayed=14.2k
R38 R39: library part CMP-0025736-4, "RES, 1.0 M, 5%, 0.1 W, AEC-Q200 Grade 0, 0603", Manufacturer=Vishay-Dale, Power_W=100mW, Supplier Part Number 1=541-1.0MGCT-ND, TempCo="200 ppm/C", Tolerance_%=5%, Value2=0.1W, Value_Code=1M00, ValueDisplayed=1.0M
R40: library part CMP-0025932-5, "RES, 5.1 k, 5%, 0.1 W, 0603", Manufacturer=Yageo, Power_W=100mW, Supplier Part Number 1=311-5.1KGRCT-ND, TempCo="100 ppm/C", Tolerance_%=5%, Value2=0.1W, Value_Code=5k10, ValueDisplayed=5.1k
R41: library part CMP-0021998-4, "RES, 10.0 k, 1%, 0.1 W, AEC-Q200 Grade 0, 0603", Manufacturer=Vishay-Dale, Power_W=100mW, Supplier Part Number 1=541-10.0KHCT-ND, TempCo="100 ppm/C", Tolerance_%=1%, Value2=0.1W, Value_Code=10k0, ValueDisplayed=10.0k
R42: library part CMP-0023718-2, "RES, 130 k, 0.1%, 0.1 W, 0603", Manufacturer="Yageo America", Power_W=100mW, TempCo="25 ppm/C", Tolerance_%=0.1%, Value2=0.1W, Value_Code=130k
R45: library part CMP-0025697-2, "RES, 0, 5%, 0.1 W, 0603", Manufacturer=Vishay-Dale, Power_W=100mW, Supplier Part Number 1=541-0.0GCT-ND, TempCo="200 ppm/C", Tolerance_%=5%, Value2=0.1W, Value_Code=0000, ValueDisplayed=0
R137: library part CMP-0022831-5, "RES, 16.0 k, 1%, 0.1 W, 0603", Manufacturer=Yageo, Power_W=100mW, Supplier Part Number 1=311-16.0KHRCT-ND, TempCo="100 ppm/C", Tolerance_%=1%, Value2=0.1W, Value_Code=16k0, ValueDisplayed=16.0k
U1: library part CMP-0074089-2, "Zero Standby PSR Flyback Controller with CVCC and Wake-Up Monitoring, D0007A (SOIC-7)", Alternate Manufacturer="Texas Instruments", Alternate PartNumber=UCC28730D
U2: library part CMP-0067258-1, "200-V Wake-up Monitor for Fast Transient Primary-side Regulation, DBV0005A (SOT-23-5)", Alternate Manufacturer="Texas Instruments", Alternate PartNumber=UCC24650DBVT
ZZ1: library part CMP-0003616-3
ZZ2: library part CMP-0077236-1
ZZ3: library part CMP-0077237-1
ZZ4: library part CMP-0077238-1

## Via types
v1: diameter 0.66, hole 0.33, Top Layer to Bottom Layer, 760 vias
v2: diameter 0.61, hole 0.203, Top Layer to Bottom Layer, tented both sides, 8 vias
v3: diameter 0.864, hole 0.406, Top Layer to Bottom Layer, tented both sides, 4 vias
v4: diameter 0.6, hole 0.3, Top Layer to Bottom Layer, 2 vias

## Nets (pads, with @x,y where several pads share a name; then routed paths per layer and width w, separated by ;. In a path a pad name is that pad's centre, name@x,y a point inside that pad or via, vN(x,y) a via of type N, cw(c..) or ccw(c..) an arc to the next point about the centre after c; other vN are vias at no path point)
AUX: D4.2 R35.2 T1.5 | length 36.2
  Bottom Layer w0.5: R35.2@96.018,6.095 R35.2@95.887,5.964 96.02,5.83 96.02,5.026 96.481,4.566 104.693,4.566 107.497,7.37 107.497,19.935 111.388,23.827 111.388,24.132 113.975,26.719 T1.5@113.975,26.834
CS: C19.2 R29.1 U1.5 | length 4.2
  Bottom Layer w0.254: R29.1@84.548,7.126 84.664,7.01 84.565,6.911 84.549,6.911 84.505,6.867 84.417,6.778 84.594,6.778 84.386,6.778 84.664,6.778 84.664,5.961 C19.2@84.689,5.936
  Bottom Layer w0.4: R29.1@84.548,7.126 U1.5@86.766,7.127
DC+: F1.2 J2.1 | length 8.1
  Top Layer w2: F1.2@3.556,54.67 3.646,54.67 5.308,53.009 J2.1@11.015,53.009
DC-: J2.2 L3.4 | length 8.4
  Bottom Layer w2.54: J2.2@18.635,53.009 19.212,52.431 19.212,47.434 L3.4@21.072,45.575
DRV: D11.1 R26.1 U1.6 | length 21.5
  Bottom Layer w0.5: R26.1@71.558,19.423 71.791,19.656 D11.1@73.312,19.656 73.312,16.967 81.882,8.397 U1.6@86.766,8.397
FLYA: C11.1 C13.1 C18.1 C20.1 C21.1 L2.1 T1.A | length 0
  Bottom Layer w1: T1.A@140.993,37.34 T1.A@141.037,37.34
  other v1: 164.973,20.94 166.141,20.94 167.31,20.94 168.478,20.94 169.647,20.94 170.815,20.94 164.389,22.108 169.062,22.108 170.231,22.108 171.399,22.108 164.973,23.276 169.647,23.276 170.815,23.276 171.983,23.276 164.389,24.445 165.557,24.445 166.726,24.445 167.894,24.445 169.062,24.445 170.231,24.445 171.399,24.445 166.141,25.613 167.31,25.613 168.478,25.613 169.647,25.613 170.815,25.613 171.983,25.613 166.726,26.782 167.894,26.782 169.062,26.782 170.231,26.782 171.399,26.782 166.141,27.95 171.983,27.95 166.141,30.287 171.983,30.287 166.726,31.455 167.894,31.455 169.062,31.455 170.231,31.455 171.399,31.455 166.141,32.624 167.31,32.624 168.478,32.624 169.647,32.624 170.815,32.624 171.983,32.624 166.726,33.792 167.894,33.792 169.062,33.792 170.231,33.792 171.399,33.792 166.141,34.96 167.31,34.96 168.478,34.96 169.647,34.96 170.815,34.96 171.983,34.96 166.726,36.129 167.894,36.129 169.062,36.129 170.231,36.129 171.399,36.129 166.141,37.297 167.31,37.297 168.478,37.297 169.647,37.297 170.815,37.297 171.983,37.297 141.021,38.466 142.189,38.466 166.726,38.466 167.894,38.466 169.062,38.466 170.231,38.466 171.399,38.466 140.437,39.634 141.605,39.634 142.773,39.634 166.141,39.634 171.983,39.634 141.021,40.802 140.437,41.971 141.605,41.971 166.141,41.971 167.31,41.971 168.478,41.971 169.647,41.971 170.815,41.971 171.983,41.971 141.021,43.139 166.726,43.139 167.894,43.139 169.062,43.139 170.231,43.139 171.399,43.139 140.437,44.308 141.605,44.308 166.141,44.308 167.31,44.308 168.478,44.308 169.647,44.308 170.815,44.308 171.983,44.308 141.021,45.476 166.726,45.476 167.894,45.476 169.062,45.476 170.231,45.476 171.399,45.476 140.437,46.644 141.605,46.644 142.773,46.644 166.141,46.644 167.31,46.644 168.478,46.644 169.647,46.644 170.815,46.644 171.983,46.644 141.021,47.813 142.189,47.813 166.726,47.813 167.894,47.813 169.062,47.813 170.231,47.813 171.399,47.813 140.437,48.981 141.605,48.981 142.773,48.981 166.141,48.981 167.31,48.981 168.478,48.981 169.647,48.981 170.815,48.981 171.983,48.981 141.021,50.15 142.189,50.15 140.437,51.318 141.605,51.318 142.773,51.318 166.141,51.318 171.983,51.318 141.021,52.486 142.189,52.486 143.358,52.486 140.437,53.655 141.605,53.655 142.773,53.655 143.942,53.655 164.973,53.655 166.141,53.655 167.31,53.655 168.478,53.655 169.647,53.655 170.815,53.655 171.983,53.655 141.021,54.823 142.189,54.823 143.358,54.823 144.526,54.823 145.694,54.823 146.863,54.823 148.031,54.823 149.2,54.823 150.368,54.823 151.536,54.823 152.705,54.823 153.873,54.823 155.042,54.823 156.21,54.823 157.378,54.823 158.547,54.823 159.715,54.823 160.884,54.823 162.052,54.823 163.22,54.823 164.389,54.823 165.557,54.823 166.726,54.823 167.894,54.823 169.062,54.823 170.231,54.823 171.399,54.823 140.437,55.992 141.605,55.992 142.773,55.992 143.942,55.992 145.11,55.992 146.279,55.992 147.447,55.992 148.615,55.992 149.784,55.992 150.952,55.992 152.121,55.992 153.289,55.992 154.457,55.992 155.626,55.992 156.794,55.992 157.963,55.992 159.131,55.992 160.299,55.992 161.468,55.992 162.636,55.992 163.805,55.992 164.973,55.992 166.141,55.992 167.31,55.992 168.478,55.992 169.647,55.992 170.815,55.992 171.983,55.992 141.021,57.16 142.189,57.16 143.358,57.16 144.526,57.16 145.694,57.16 146.863,57.16 148.031,57.16 149.2,57.16 150.368,57.16 151.536,57.16 152.705,57.16 153.873,57.16 155.042,57.16 156.21,57.16 157.378,57.16 158.547,57.16 159.715,57.16 160.884,57.16 162.052,57.16 163.22,57.16 164.389,57.16 165.557,57.16 166.726,57.16 167.894,57.16 169.062,57.16 170.231,57.16 171.399,57.16 140.437,58.328 141.605,58.328 142.773,58.328 143.942,58.328 145.11,58.328 146.279,58.328 147.447,58.328 148.615,58.328 149.784,58.328 150.952,58.328 152.121,58.328 153.289,58.328 154.457,58.328 155.626,58.328 156.794,58.328 157.963,58.328 159.131,58.328 160.299,58.328 161.468,58.328 162.636,58.328 163.805,58.328 164.973,58.328 166.141,58.328 167.31,58.328 168.478,58.328 169.647,58.328 170.815,58.328 141.021,59.497 142.189,59.497 143.358,59.497 144.526,59.497 145.694,59.497 146.863,59.497 148.031,59.497 149.2,59.497 150.368,59.497 151.536,59.497 152.705,59.497 153.873,59.497 155.042,59.497 156.21,59.497 157.378,59.497 158.547,59.497 159.715,59.497 160.884,59.497 162.052,59.497 163.22,59.497 164.389,59.497 165.557,59.497 166.726,59.497 167.894,59.497 169.062,59.497 170.231,59.497
FLYB: D7.2 R27.1 R31.2 T1.B | length 8.9
  Bottom Layer w1: T1.B@141.493,31.834 141.789,31.539 141.789,29.533 143.291,28.03 143.456,28.03 143.591,27.895 143.591,25.695 R31.2@144.842,24.444
NetC1_2: C1.2 C2.2 D1.1 D22.1 R5.1 | length 20.7
  Bottom Layer w1: R5.1@93.331,49.512 D22.1@98.206,49.512 ; D22.1@98.136,49.132 98.586,49.132 99.286,48.432 99.286,47.454 100.427,46.313 103.946,46.313 D1.1@104.018,46.384 ; 104.018,49.899 D1.1@104.018,46.384 ; D1.1@104.853,46.964 104.274,46.384 D1.1@104.018,46.384 ; C2.2@105.044,49.899 105.194,50.049 C2.2@105.469,50.049 105.466,50.052 C1.2@102.98,50.052 ; C1.2@102.98,50.052 102.705,50.052 C1.2@102.702,50.055 102.977,50.055 C1.2@102.98,50.052
NetC7_1: C7.1 D8.1 Q1.1 R22.2 | length 15.6
  Bottom Layer w1: R22.2@86.862,26.607 87.137,26.607 88.846,26.607 89.368,27.128 89.368,27.422 89.503,27.557 C7.1@89.668,27.557 ; C7.1@89.764,27.525 92.971,27.525 93.366,27.131 Q1.1@96.808,27.131 96.683,27.005 93.366,27.005 91.912,27.005 D8.1@91.867,26.96
NetC7_2: C7.2 D8.2 Q1.3 Q2.2 | length 32.1
  Top Layer w0.254: Q1.3@96.332,32.211 Q1.3@96.772,32.65
  Bottom Layer w1: Q2.2@80.289,21.356 80.289,21.572 81.299,22.582 81.299,22.911 ; C7.2@89.668,29.589 89.803,29.724 91.348,29.724 91.86,30.235 D8.2@91.867,30.235 D8.2@91.867,30.235 91.862,30.242 91.862,32.294 92.125,32.557
  Bottom Layer w1.5: 81.299,22.911 81.299,25.366 80.808,25.858 80.808,30.617 82.747,32.557 92.125,32.557 95.208,32.557 95.212,32.561 Q1.3@96.692,32.561
NetC8_2: C8.2 R3.2 R36.1 R137.2 U1.2 | length 8.8
  Bottom Layer w0.254: U1.2@92.216,9.667 94.418,9.667 94.868,9.217 R137.2@95.886,9.217 ; C8.2@95.875,12.551 95.886,12.54 R3.2@95.886,10.666 R137.2@95.886,9.217 ; R36.1@95.887,7.659 95.887,9.216 R137.2@95.886,9.217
